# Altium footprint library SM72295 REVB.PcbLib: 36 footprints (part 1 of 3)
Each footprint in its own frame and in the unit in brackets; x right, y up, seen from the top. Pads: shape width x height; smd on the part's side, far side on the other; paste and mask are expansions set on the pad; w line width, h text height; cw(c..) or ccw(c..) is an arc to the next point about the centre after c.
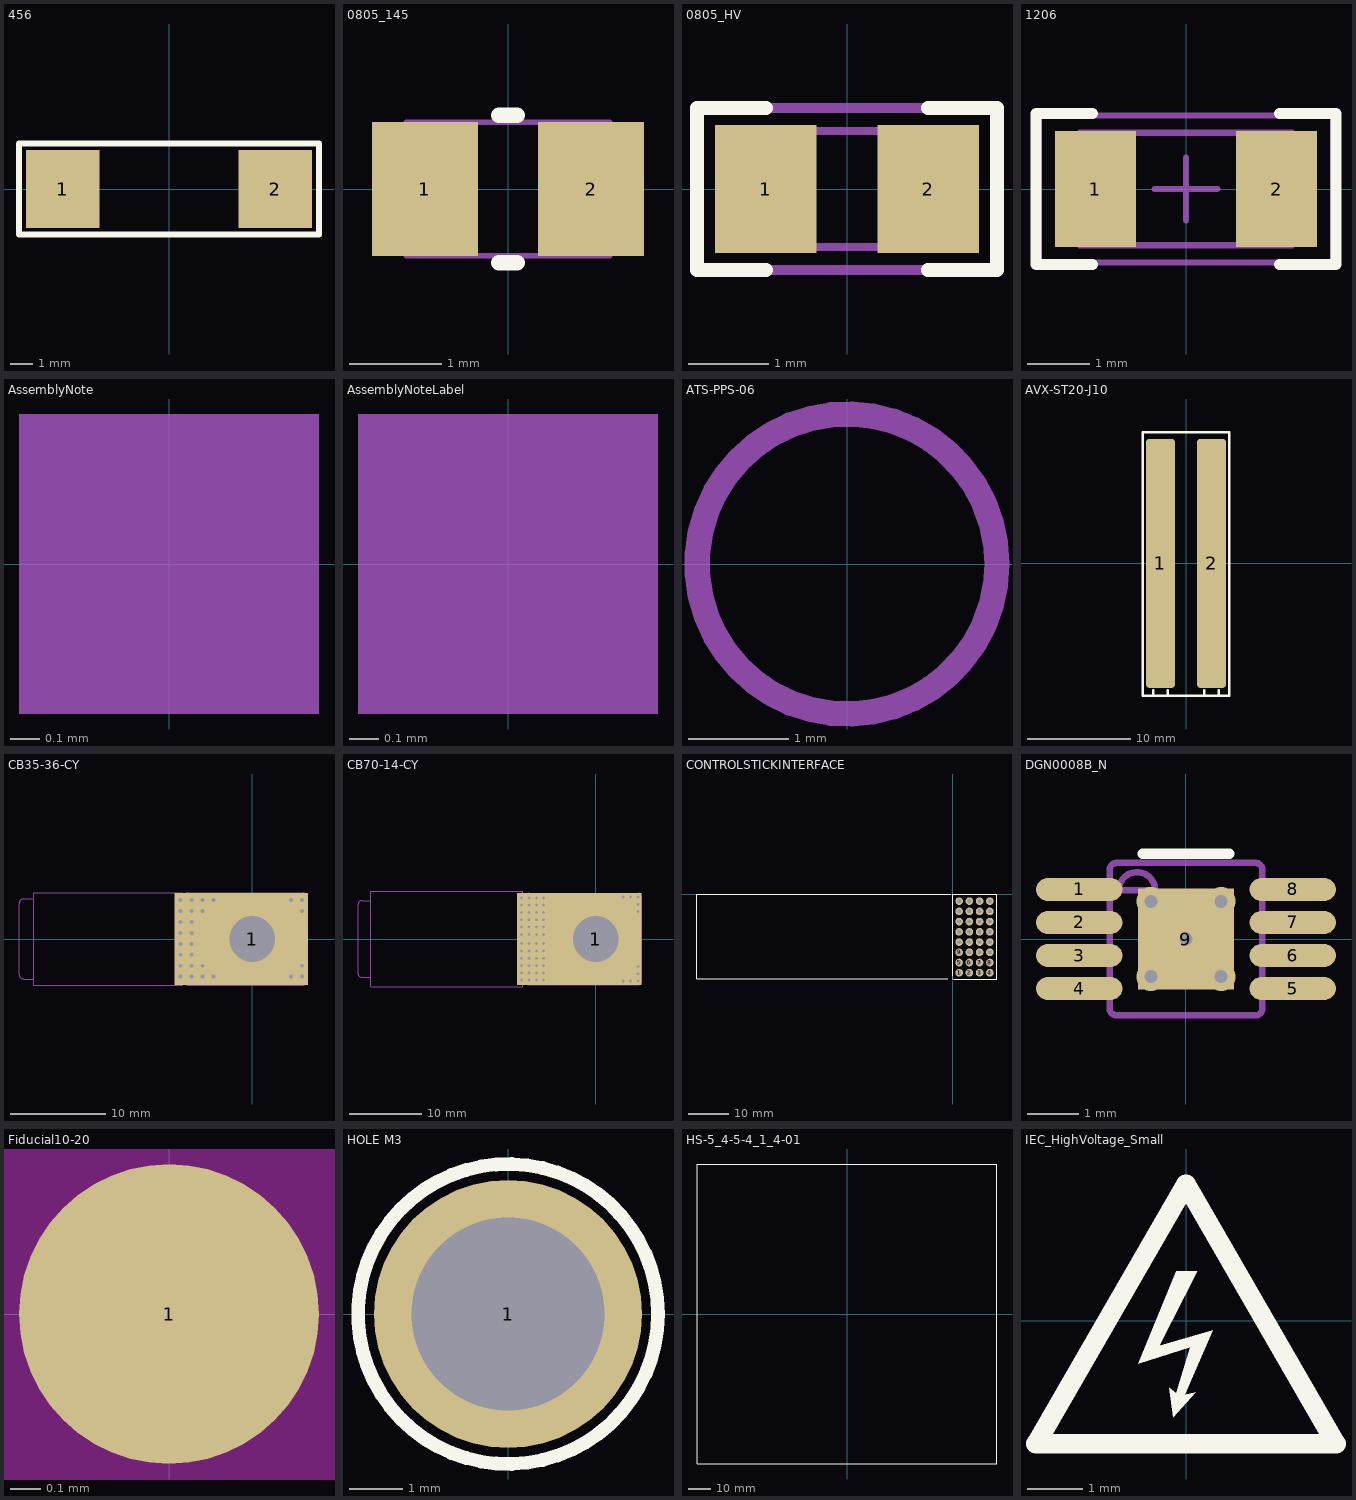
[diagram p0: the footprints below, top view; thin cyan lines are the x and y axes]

## 456 [mm] "LITTELFUSE 456 SERIES FUSE"
height 3.12
pads (2):
  rect 3.25x3.44 smd: 1(-4.675,0) 2(4.675,0)
Top Overlay:
  lines w0.254: -6.6,-2 6.6,-2 6.6,2 -6.6,2 -6.6,-2
Mechanical 5:
  text ".Designator" at 1.143,0.508 h0.76
3D body: height 3.12, standoff 0, extent -6.6,-2 6.6,2

## 0805_145 [mm] "0805 / 1.45mm height"
height 1.45
pads (2):
  rect 1.15x1.45 smd: 1(-0.9,0) 2(0.9,0)
Top Overlay:
  lines w0.17: -0.1,-0.8 0.1,-0.8 ; -0.1,0.8 0.1,0.8
Mechanical 5:
  lines w0.06: -1.1,-0.725 -1.1,0.725 1.1,0.725 1.1,-0.725 -1.1,-0.725
  text ".Designator" at -0.508,-0.254 h0.53
3D body: height 1.4, standoff 0, extent 0.501,-0.724 1.099,0.724
3D body: height 1.45, standoff 0, extent -0.499,-0.724 0.5,0.725
3D body: height 1.4, standoff 0, extent -1.099,-0.724 -0.501,0.724

## 0805_HV [mil] "0805 with 30mil clearance between pads"
height 43.31
pads (2):
  rect 50x63 smd: 1(-40,0) 2(40,0)
Top Overlay:
  lines w7: -40,-40 -74,-40 -74,0 -74,40 -40,40 ; 40,-40 74,-40 74,0 74,40 40,40
Mechanical 5:
  lines w5: -74,-40 74,-40 74,40 -74,40 -74,-40
  text ".Designator" at -50,-15 h35
Mechanical 13:
  lines w3.94: -25.59,-28.54 -25.59,28.54 ; 25.59,-28.54 25.59,28.54 ; -43.31,-28.54 -43.31,28.54 43.31,28.54 43.31,-28.54 -43.31,-28.54
3D body: height 43.31, standoff 0, extent 25.61,-28.52 43.29,28.52
3D body: height 43.31, standoff 0, extent -25.57,-28.52 25.57,28.52
3D body: height 43.31, standoff 0, extent -43.29,-28.52 -25.61,28.52

## 1206 [mm] "1206 from SM-752 data"
height 1.35
pads (2):
  rect 1.3x1.85 smd: 1(-1.45,0) 2(1.45,0)
Top Overlay:
  lines w0.178: -1.5,-1.21 -2.4,-1.21 -2.4,1.21 -1.5,1.21 ; 1.5,-1.21 2.4,-1.21 2.4,1.21 1.5,1.21
Mechanical 5:
  lines w0.1: -1.7,-0.9 -1.7,0.9 1.7,0.9 1.7,-0.9 -1.7,-0.9
  text ".Designator" at 1.2,0.381 h0.81
Mechanical 13:
  lines w0.1: -1.2,-0.9 -1.2,0.9 ; 1.2,-0.9 1.2,0.9 ; -1.7,-0.9 -1.7,0.9 1.7,0.9 1.7,-0.9 -1.7,-0.9
Mechanical 15:
  lines w0.1: -0.5,0 0.5,0 ; 0,-0.5 0,0.5 ; -2.35,-1.175 -2.35,1.175 2.35,1.175 2.35,-1.175 -2.35,-1.175
3D body: height 1.35, standoff 0, extent 1.201,-0.899 1.699,0.899
3D body: height 1.35, standoff 0, extent -1.199,-0.899 1.199,0.899
3D body: height 1.35, standoff 0, extent -1.699,-0.899 -1.201,0.899

## AssemblyNote [mil] "Assembly Note"
Mechanical 5:
  rectangle: -20,-20 20,20
  text ".Comment" at 45,-20 h30
  text ".Designator" at -165,-20 h30

## AssemblyNoteLabel [mil] "Assembly Note for PCB Labels"
Mechanical 5:
  rectangle: -20,-20 20,20
  text "Install label in silkscreened box after final wash.  Text shall be 8 pt font.  Text shall be per the Label Table in the PDF schematic." at 45,-20 h30
  text ".Designator" at -165,-20 h30

## ATS-PPS-06 [mil] "ATS PUSH PIN SPRING ATS-PPS-06"
height 250
Mechanical 5:
  text ".Designator" at -50,-20 h30
Mechanical 13:
  circle w10: c0,0 r59.06

## AVX-ST20-J10 [mil]
pads (2):
  rrect20% 110x950 smd: 1(-97.5,0) 2(97.5,0)
Top Overlay:
  lines w10: -125,-505 -125,-485 ; -70,-505 -70,-485 ; 70,-505 70,-485 ; 125,-505 125,-485 ; -165,-505 165,-505 165,500 -165,500 -165,-505
3D body: height 285, standoff 0, extent -165,-505 165,500

## CB35-36-CY [mil] "Terminal 50A Lug"
height 750
pads (1):
  rect 550x380 hole 188 copper offset -45,0 paste-190: 1(0,0)
via 160,-155 diameter 32 hole 16
via 205,-155 diameter 32 hole 16
via 205,-110 diameter 32 hole 16
via 160,160 diameter 32 hole 16
via 205,160 diameter 32 hole 16
via 205,115 diameter 32 hole 16
via -160,160 diameter 32 hole 16
via -295,-20 diameter 32 hole 16
via -250,160 diameter 32 hole 16
via -250,115 diameter 32 hole 16
via -295,160 diameter 32 hole 16
via -205,160 diameter 32 hole 16
via -250,70 diameter 32 hole 16
via -295,115 diameter 32 hole 16
via -205,115 diameter 32 hole 16
via -250,25 diameter 32 hole 16
via -250,-20 diameter 32 hole 16
via -295,25 diameter 32 hole 16
via -295,70 diameter 32 hole 16
via -295,-65 diameter 32 hole 16
via -250,-65 diameter 32 hole 16
via -295,-110 diameter 32 hole 16
via -250,-110 diameter 32 hole 16
via -205,-110 diameter 32 hole 16
via -295,-155 diameter 32 hole 16
via -250,-155 diameter 32 hole 16
via -205,-155 diameter 32 hole 16
via -160,-155 diameter 32 hole 16
Mechanical 5:
  lines w5: -900,-164.84 -940.4,-164.84 cw(c-940.4,-144.84) -960.4,-144.84 -960.4,144.84 cw(c-940.4,144.84) -940.4,164.84 -900,164.84 ; -285.4,-170 ccw(c-265.4,-170) -265.4,-190 -200.4,-190 209.6,-190 ccw(c209.6,-170) 229.6,-170 229.6,170 ccw(c209.6,170) 209.6,190 -200.4,190 -265.4,190 ccw(c-265.4,170) -285.4,170 ; -285.4,-170 -285.4,170 ; -285.4,-170 -285.4,-190 -900,-190 -900,-170 -900,170 -900,190 -285.4,190 -285.4,170
  text ".Designator" at -40,-25 h60
3D body: height 614.43, standoff 0, extent -960,-189 230,191

## CB70-14-CY [mil] "Terminal 90A Lug"
height 750
pads (1):
  rect 680x500 hole 250 copper offset -90,0 paste-250: 1(0,0)
via -405,-225 diameter 32 hole 16
via -365,-185 diameter 32 hole 16
via -405,-185 diameter 32 hole 16
via -405,-145 diameter 32 hole 16
via -365,-105 diameter 32 hole 16
via -365,-65 diameter 32 hole 16
via -405,-65 diameter 32 hole 16
via -405,-25 diameter 32 hole 16
via -365,-25 diameter 32 hole 16
via -365,25 diameter 32 hole 16
via -405,25 diameter 32 hole 16
via -365,65 diameter 32 hole 16
via -405,65 diameter 32 hole 16
via -365,105 diameter 32 hole 16
via -405,105 diameter 32 hole 16
via -405,145 diameter 32 hole 16
via -365,185 diameter 32 hole 16
via -365,225 diameter 32 hole 16
via 230,190 diameter 32 hole 16
via 150,230 diameter 32 hole 16
via 230,230 diameter 32 hole 16
via 190,230 diameter 32 hole 16
via 230,150 diameter 32 hole 16
via 230,-230 diameter 32 hole 16
via 230,-150 diameter 32 hole 16
via 230,-190 diameter 32 hole 16
via 190,-230 diameter 32 hole 16
via 150,-230 diameter 32 hole 16
via -405,-105 diameter 32 hole 16
via -405,225 diameter 32 hole 16
via -405,185 diameter 32 hole 16
via -365,-225 diameter 32 hole 16
via -365,-145 diameter 32 hole 16
via -365,145 diameter 32 hole 16
via -285,145 diameter 32 hole 16
via -285,-145 diameter 32 hole 16
via -285,-225 diameter 32 hole 16
via -325,185 diameter 32 hole 16
via -325,225 diameter 32 hole 16
via -325,-105 diameter 32 hole 16
via -285,225 diameter 32 hole 16
via -285,185 diameter 32 hole 16
via -325,145 diameter 32 hole 16
via -325,105 diameter 32 hole 16
via -285,105 diameter 32 hole 16
via -325,65 diameter 32 hole 16
via -285,65 diameter 32 hole 16
via -325,25 diameter 32 hole 16
via -285,25 diameter 32 hole 16
via -285,-25 diameter 32 hole 16
via -325,-25 diameter 32 hole 16
via -325,-65 diameter 32 hole 16
via -285,-65 diameter 32 hole 16
via -285,-105 diameter 32 hole 16
via -325,-145 diameter 32 hole 16
via -325,-185 diameter 32 hole 16
via -285,-185 diameter 32 hole 16
via -325,-225 diameter 32 hole 16
Mechanical 5:
  lines w5: -1230,-209.04 -1279.23,-209.04 cw(c-1279.23,-189.04) -1299.23,-189.04 -1299.23,189.03 cw(c-1279.23,189.03) -1279.23,209.03 -1230,209.03 ; -398.88,-178.14 -384.23,-178.14 ; -398.88,178.14 -384.23,178.14 ; -1230,-260 -398.88,-260 -398.88,-220 -398.88,220 -398.88,260 -1230,260 -1230,220 -1230,-220 -1230,-260 ; -384.23,-230 ccw(c-364.23,-230) -364.23,-250 -289.23,-250 230.77,-250 ccw(c230.77,-230) 250.77,-230 250.77,230 ccw(c230.77,230) 230.77,250 -289.23,250 -364.23,250 ccw(c-364.23,230) -384.23,230 -384.23,-230
  text ".Designator" at 50,30 h60
3D body: height 714.44, standoff 0, extent -1300,-260 250,260

## CONTROLSTICKINTERFACE [mil] "USE TWO SAMTEC SSW-108-01-T-D IN PARALLEL"
height 350
pads (33):
  round 80 on Top Overlay: 0(0,-830)
  round 75 hole 42: 1(60,-765) 2(160,-765) 3(260,-765) 4(360,-765) 5(60,-665) 6(160,-665) 7(260,-665) 8(360,-665) 9(60,-565) 10(160,-565) 11(260,-565) 12(360,-565) 13(60,-465) 14(160,-465) 15(260,-465) 16(360,-465) 17(60,-365) 18(160,-365) 19(260,-365) 20(360,-365) 21(60,-265) 22(160,-265) 23(260,-265) 24(360,-265) 25(60,-165) 26(160,-165) 27(260,-165) 28(360,-165) 29(60,-65) 30(160,-65) 31(260,-65) 32(360,-65)
Top Overlay:
  lines w10: -50,-825 -2500,-825 -2500,0 -20,0 ; 0,-830 430,-830 430,0 0,0 0,-830
3D body: height 350, standoff 0, extent 0,-830 430,0

## DGN0008B_N [mm] "TSOP, 8-Leads, Body 3x3mm, Pitch 0.65mm, Thermal Pad 1.92x1.60mm, IPC Medium Density"
height 1.1
pads (9):
  oval 1.7x0.45 smd mask+0.05: 1(-2.1,0.975) 2(-2.1,0.325) 3(-2.1,-0.325) 4(-2.1,-0.975) 5(2.1,-0.975) 6(2.1,-0.325) 7(2.1,0.325) 8(2.1,0.975)
  rect 1.88x1.98 smd: 9(0,0)
via 0,0 diameter 0.559 hole 0.254
via -0.69,0.74 diameter 0.559 hole 0.254
via 0.69,0.74 diameter 0.559 hole 0.254
via -0.69,-0.74 diameter 0.559 hole 0.254
via 0.69,-0.74 diameter 0.559 hole 0.254
Top Overlay:
  lines w0.2: -0.85,1.675 0.85,1.675
Mechanical 5:
  lines w0.127: -2.45,-1.131 -2.21,-1.131 -2.09,-1.131 -2.087,-1.131 -1.784,-1.131 -1.498,-1.131 -1.498,-0.826 -1.784,-0.826 -2.087,-0.826 -2.09,-0.826 -2.21,-0.826 -2.45,-0.826 -2.45,-1.131 ; -2.45,-0.48 -2.21,-0.48 -2.09,-0.48 -2.087,-0.48 -1.784,-0.48 -1.498,-0.48 -1.498,-0.175 -1.784,-0.175 -2.087,-0.175 -2.09,-0.175 -2.21,-0.175 -2.45,-0.175 -2.45,-0.48 ; -2.45,0.17 -2.21,0.17 -2.09,0.17 -2.087,0.17 -1.784,0.17 -1.498,0.17 -1.498,0.475 -1.784,0.475 -2.087,0.475 -2.09,0.475 -2.21,0.475 -2.45,0.475 -2.45,0.17 ; -2.45,0.82 -2.21,0.82 -2.09,0.82 -2.087,0.82 -1.784,0.82 -1.498,0.82 -1.498,1.125 -1.784,1.125 -2.087,1.125 -2.09,1.125 -2.21,1.125 -2.45,1.125 -2.45,0.82 ; -1.497,-1.377 ccw(c-1.37,-1.374) -1.373,-1.501 -1.371,-1.501 1.373,-1.501 1.375,-1.501 ccw(c1.373,-1.374) 1.5,-1.377 1.5,-1.374 1.5,1.369 1.5,1.372 ccw(c1.373,1.369) 1.375,1.496 1.373,1.496 -1.371,1.496 -1.373,1.496 ccw(c-1.37,1.369) -1.497,1.372 -1.498,1.369 -1.498,-1.374 -1.497,-1.377 ; -1.32,0.962 cw(c-0.964,0.962) -0.609,0.962 -1.32,0.962 ; 1.5,-1.131 1.786,-1.131 2.089,-1.131 2.093,-1.131 2.213,-1.131 2.452,-1.131 2.452,-0.826 2.213,-0.826 2.093,-0.826 2.089,-0.826 1.786,-0.826 1.5,-0.826 1.5,-1.131 ; 1.5,-0.48 1.786,-0.48 2.089,-0.48 2.093,-0.48 2.213,-0.48 2.452,-0.48 2.452,-0.175 2.213,-0.175 2.093,-0.175 2.089,-0.175 1.786,-0.175 1.5,-0.175 1.5,-0.48 ; 1.5,0.17 1.786,0.17 2.089,0.17 2.093,0.17 2.213,0.17 2.452,0.17 2.452,0.475 2.213,0.475 2.093,0.475 2.089,0.475 1.786,0.475 1.5,0.475 1.5,0.17 ; 1.5,0.82 1.786,0.82 2.089,0.82 2.093,0.82 2.213,0.82 2.452,0.82 2.452,1.125 2.213,1.125 2.093,1.125 2.089,1.125 1.786,1.125 1.5,1.125 1.5,0.82
  text ".Designator" at -0.125,1.15 h0.64
Mechanical 15:
  lines w0.1: -0.5,0 0.5,0 ; 0,-0.5 0,0.5
3D body: height 0.94, standoff -0.02, extent -2.451,-1.499 2.451,1.498

## Fiducial10-20 [mm]
pads (1):
  round 1 smd mask+0.5: 1(0,0)
Top Layer keep-out:
  circle w1.178: c0,0 r0.5

## HOLE M3 [mm] "M3 X0.5 HOLE NO METAL"
height 2.4
pads (1):
  round 5 hole 3.6: 1(0,0)
Top Overlay:
  circle w0.254: c0,0 r2.8
Mechanical 5:
  text ".Designator" at -0.1,-0.1 h1.02
3D body: height 2.5, standoff 0, extent -4.356,-4.3 4.3,4.3

## HS-5_4-5-4_1_4-01 [mil] "HS5.4-5.4-1.4-01 HEATSINK cUSTOM THERMOELECTRIC"
height 1375
pads (1):
  round 60 on Top Overlay: 0(0,0)
Top Overlay:
  lines w20: -2687.5,-2687.5 -2687.5,2687.5 2687.5,2687.5 2687.5,-2687.5 -2687.5,-2687.5
Mechanical 5:
  text ".Designator" at -3.94,-3.94 h30
3D body: height 1375, standoff 0, extent -2680,-2685 2695,2695

## IEC_HighVoltage_Small [mil]
Top Overlay:
  region: -7,35 8,35 -19,-18 19,-7 -1,-53 7,-51 -9,-69 -12,-48 -7,-52 3,-19 -34,-31
  lines w14: -107,-88 0,97.33 107,-88 -107,-88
